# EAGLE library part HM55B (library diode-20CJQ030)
Hitachi® HM55B General Description The Hitachi HM55B is a dual-axis magnetic field sensor that can add a sense of direction to your next electronic or robotic project. . Features Sensitive to microtesla (µT) variations in magnetic field strength Simplifies direction by resolving magnetic field measurements into two component axes Good for 6-bit (64-direction) resolution measurements after software calibration Only 30 to 40 ms between start measurement and data-ready Built-in resistor protection for data pins eliminates bus conflict risks Compact and breadboard-friendly Application Ideas Mobile robot direction sensor Handheld electronic compass Weathervane indicator for remote weather stations Audible compass for the vision impaired Automotive electronic compass Please send any comments to: messi@users.sourceforge.net
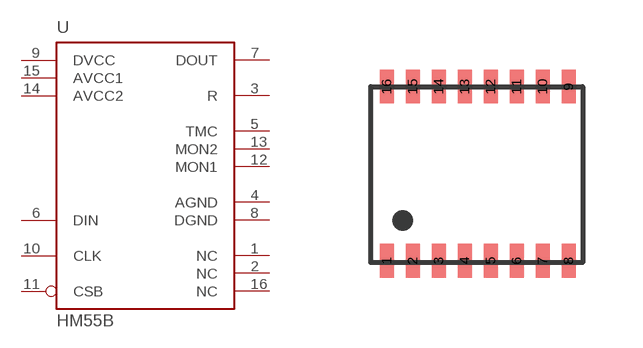
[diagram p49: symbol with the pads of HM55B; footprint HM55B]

Designator prefix U

## HM55B  [HM55B]
1  NC  nc
2  NC  nc
3  R  in
4  AGND  pwr
5  TMC  in
6  DIN  in
7  DOUT  out
8  DGND  pwr
9  DVCC  pwr
10  CLK  in
11  CSB  in
12  MON1  in
13  MON2  in
14  AVCC2  pwr
15  AVCC1  pwr
16  NC  nc

## Footprint HM55B (pad centres in mm)
Package for the HM55B from Hitachi
smd 0.35 x 0.85: 1 -2.25,-2.15; 2 -1.6,-2.15; 3 -0.95,-2.15; 4 -0.3,-2.15; 5 0.35,-2.15; 6 1,-2.15; 7 1.65,-2.15; 8 2.3,-2.15; 9 2.3,2.2; 10 1.65,2.2; 11 1,2.2; 12 0.35,2.2; 13 -0.3,2.2; 14 -0.95,2.2; 15 -1.6,2.2; 16 -2.25,2.2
